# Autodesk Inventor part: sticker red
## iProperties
Shininess: 64.0
Length Units: 11269
Angle Units: 11279
Time Units: 11290
Mass Units: 11283
Length Display Precision: 3
Angle Display Precision: 2
Compacted: True
Part Number: sticker red
Document SubType Name: Modeling
Created: 2004-10
Material: Standard
Designer: W. Holzwarth
Manufacturer: Standard
Standards Organization: Custom
Density: 0.0
Volumn: 0.0
Area: 0.0
PropertySet Name: Model Information
Control State: 0
Master: False
Checked Out: False
Author: W. Holzwarth
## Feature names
1. Basis1
